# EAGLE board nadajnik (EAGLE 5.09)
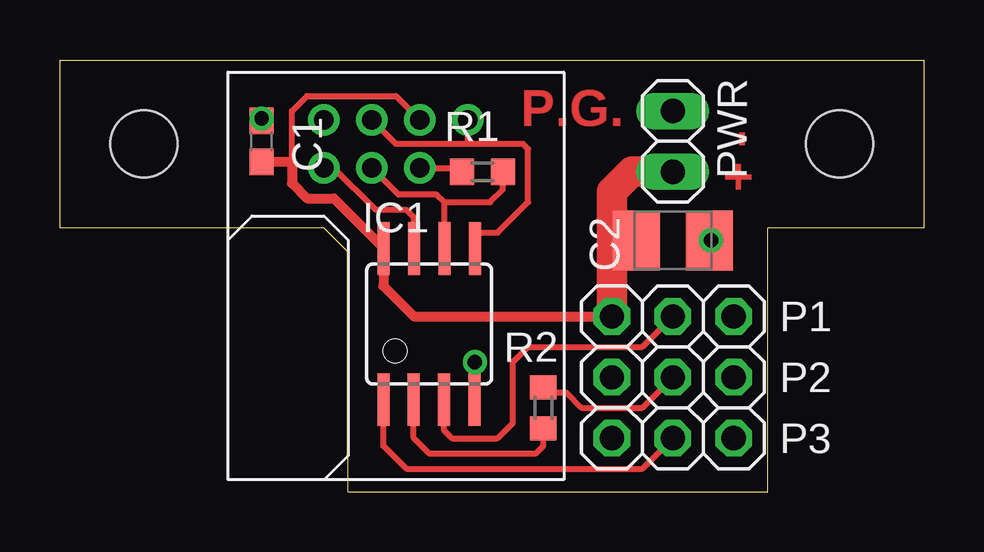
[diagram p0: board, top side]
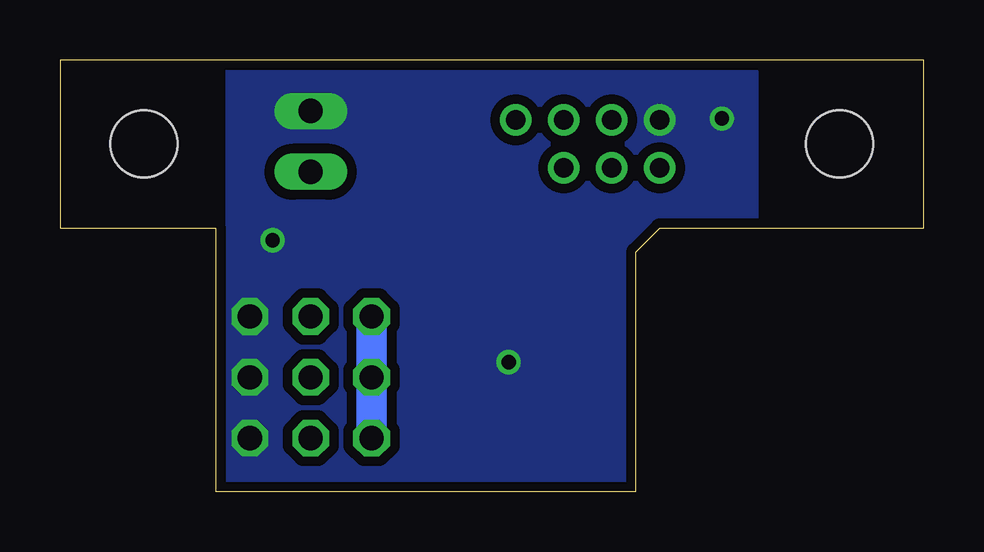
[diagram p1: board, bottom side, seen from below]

Size 36 x 18 mm. Coordinates in mm from the lower left corner, seen from the top.
Outline: 12,0 29.5,0 29.5,11 36,11 36,18 0,18 0,11 11,11 12,10 12,0
Copper layers (1*16): Top 0.035mm / dielectric 1.5mm / Bottom 0.035mm
Design rules "default *": minimum track width 10mil, minimum drill 24mil, track to track 8mil, track to pad 8mil, pad to pad 8mil, via to via 8mil, smd to smd 8mil, copper to edge 1mil, drill to drill 8mil, minimum pad ring 10mil, minimum via ring 8mil, stop-mask expansion 4mil, vias tented up to drill 0mil, thermal gap 10mil
Holes 2.8 mm at 3.5,14.5 32.5,14.5

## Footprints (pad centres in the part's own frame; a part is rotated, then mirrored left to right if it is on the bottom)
C0603 = smd 1.1 x 1: 1 -0.85,0; 2 0.85,0
B/3528-21R = smd 1.95 x 2.5: + 1.525,0; - -1.525,0
SOIC8 = smd 0.5 x 2.2: 1 -1.905,-3.154; 2 -0.645,-3.154; 3 0.625,-3.154; 4 1.895,-3.154; 5 1.905,3.154; 6 0.635,3.154; 7 -0.635,3.154; 8 -1.905,3.154
PINHEAD-1X3 = drill 1.016 octagon: 1 -2.54,0; 2 0,0; 3 2.54,0
1X02 = drill 1.016 long: 1 -1.27,0; 2 1.27,0
R0603 = smd 1 x 1.1: 1 -0.85,0; 2 0.85,0
RFM02M = drill 0.8 round: 1 6,2; 2 4,2; 3 2,2; 4 0,2; 5 0,0; 6 2,0; 7 4,0

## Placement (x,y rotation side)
C1  100nF  [C0603]  8.4,14.61 90 top
C2  47uF/10V  [B/3528-21R]  25.55,10.48 180 top
IC1  ATTINY13  [SOIC8]  15.39,6.99 0 top
P1  10k  [PINHEAD-1X3]  25.55,7.3 0 top
P2  10k  [PINHEAD-1X3]  25.55,4.76 0 top
P3  10k  [PINHEAD-1X3]  25.55,2.22 0 top
PWR  [1X02]  25.55,14.61 270 top
R1  4k7  [R0603]  17.61,13.34 180 top
R2  4k7  [R0603]  20.15,3.49 90 top
RFM02  [RFM02M]  11,13.5 0 top

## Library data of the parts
C1 C2 R1 R2 = rcl
IC1 = avr
P1-P3 RFM02 = gogo
PWR = pinhead

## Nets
GND: C1.2 C2.- IC1.4 P1.3 P2.3 P3.3 PWR.1 RFM02.4
N$1: IC1.1 P3.2
N$2: P2.2 R2.2
N$3: IC1.3 P1.2
N$4: IC1.7 RFM02.5
N$5: IC1.2 R2.1
N$17: IC1.6 R1.1 RFM02.6
N$19: IC1.5 RFM02.1 RFM02.3
N$26: R1.2 RFM02.7
VCC: C1.1 C2.+ IC1.8 P1.1 P2.1 P3.1 PWR.2 RFM02.2

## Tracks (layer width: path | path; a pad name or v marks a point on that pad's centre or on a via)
GND  (via drill 0.6)
  Top 0.406: C1.2 v8.4,15.56 | IC1.4 v17.3,5.4 | C2.- v27.14,10.48
  pour Bottom (isolate 0.406, no thermals): 7,0.5 7,17.5 29,17.5 29,0.5
N$1
  Top 0.254: P3.2 24.28,0.95 14.44,0.95 13.48,1.91 IC1.1
N$2
  Top 0.254: P2.2 24.28,3.49 21.74,3.49 21.11,4.13 20.15,4.13 R2.2
N$3
  Top 0.254: IC1.3 16.02,2.55 16.34,2.22 18.25,2.22 18.88,2.86 18.88,5.4 19.52,6.03 24.28,6.03 P1.2
N$4
  Top 0.254: IC1.7 14.76,11.43 14.44,11.75 13.17,11.75 11.41,13.5 RFM02.5
N$5
  Top 0.254: IC1.2 14.74,2.23 15.39,1.59 19.84,1.59 20.15,1.91 R2.1
N$17
  Top 0.254: IC1.6 16.02,12.06 | 16.02,12.06 15.71,12.38 14.12,12.38 RFM02.6 | 16.02,12.06 17.93,12.06 18.46,12.6 R1.1
N$19
  Top 0.254: RFM02.3 14,14.5 17,14.5 | 17,14.5 RFM02.1 | 17,14.5 19.3,14.5 19.52,14.29 19.52,12.06 18.25,10.79 17.3,10.79 IC1.5
N$26
  Top 0.254: R1.2 16.76,13.5 RFM02.7
VCC
  Top 0.254: RFM02.2 14,16.5 10.3,16.5 9.68,15.88 9.68,13.76
  Top 0.406: C1.1 9.68,13.76 9.68,12.86 10.31,12.22 11.42,12.22 13.48,10.16 IC1.8 13.48,8.57 14.76,7.3 P1.1
  Top 1.27: P1.1 23.01,10.48 | PWR.2 23.84,13.34 23.01,12.51 23.01,10.48 | 23.01,10.48 C2.+
  Bottom 1.27: P3.1 P2.1 P1.1

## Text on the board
Top: P.G. | + -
